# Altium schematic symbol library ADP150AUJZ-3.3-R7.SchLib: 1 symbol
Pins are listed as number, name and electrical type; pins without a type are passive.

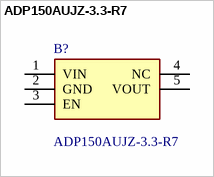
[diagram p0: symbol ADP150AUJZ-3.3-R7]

## ADP150AUJZ-3.3-R7
designator B?
Ultralow Noise, 150 mA CMOS Linear Regulator; Manufacturer_Name: Analog Devices; Geometry.Height: 1mm
footprint SOT95P280X100-5N
pins: 1 VIN, 2 GND, 3 EN, 4 NC, 5 VOUT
